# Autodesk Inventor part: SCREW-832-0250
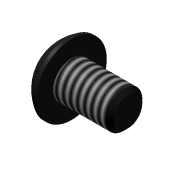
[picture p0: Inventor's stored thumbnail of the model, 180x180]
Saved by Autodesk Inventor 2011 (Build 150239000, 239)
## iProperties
Created: 2007-08
Part Number: SCREW-832-0250
Material: Stainless Steel
Document SubType Name: Modeling
Density: 8.08 g/cm^3
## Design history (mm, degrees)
feature "Base1"
thread "Thread1" dims "d0" = 25.4, "d1" = 0
body "Solid1"
